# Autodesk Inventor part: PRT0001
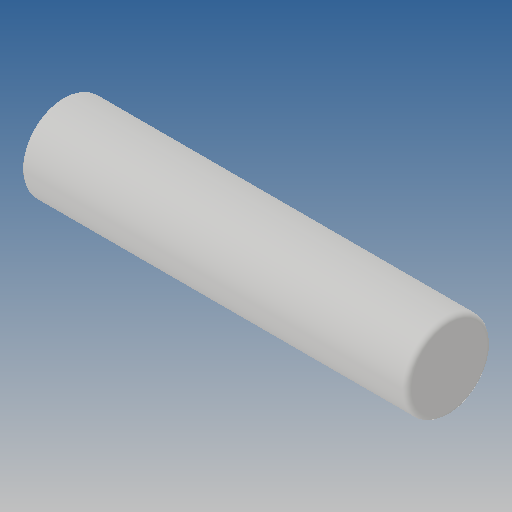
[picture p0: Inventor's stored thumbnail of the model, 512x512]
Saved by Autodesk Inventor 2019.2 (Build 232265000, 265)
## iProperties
Created: 2010-02
Part Number: PRT0001
Material: Ogólny
Document SubType Name: Modeling
Designer: CADENGINEERING4
Density: 1 g/cm^3
Appearance: Domyślna
Author: CADENGINEERING4
Revision Number: 1LAST_VERSION
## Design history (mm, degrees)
feature "Baza1"
node "Bryła1"
